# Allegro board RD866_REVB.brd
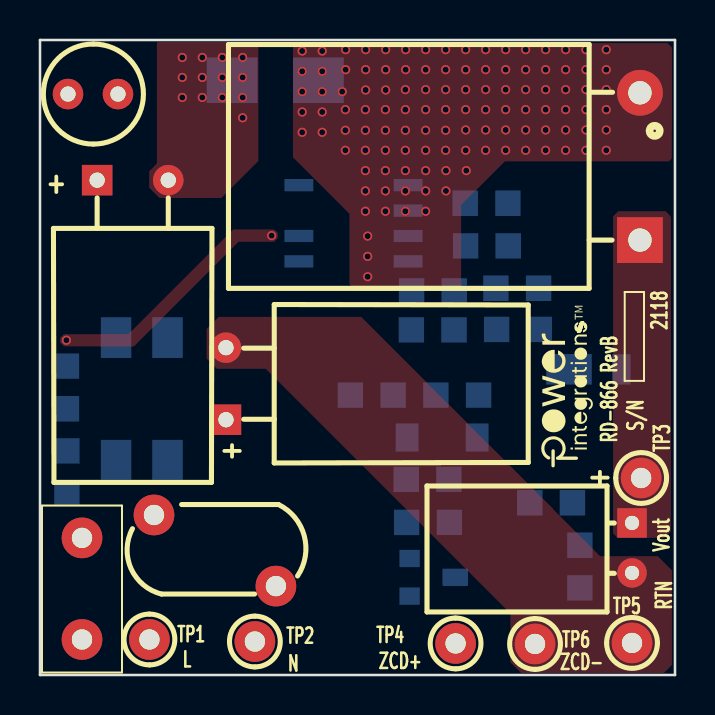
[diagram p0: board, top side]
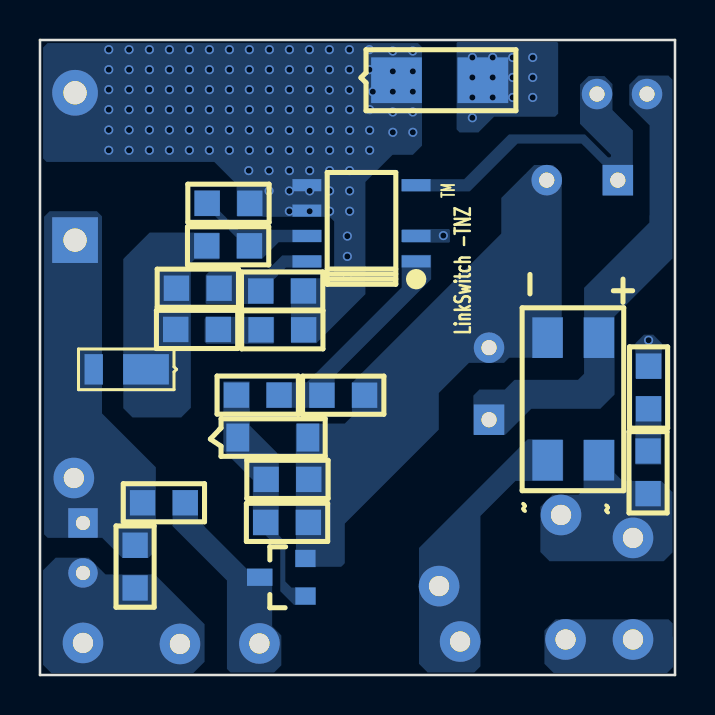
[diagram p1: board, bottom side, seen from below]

Outline 31.75 x 31.75 mm; copper layers: TOP, BOTTOM. Coordinates in mm from the lower left corner of the outline.
Outline path: 0,31.75 0,0 31.75,0 31.75,31.75 0,31.75

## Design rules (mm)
constraint set DEFAULT: min track width 0.508

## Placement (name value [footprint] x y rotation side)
BR1  B10S-G  [PISMSOIC4]  6.37 10.74 180 bottom
C1  2.2 uF  [PIPOLCAPCLYD320LS140030430H]  9.3 14.56 270 top
C2  2.2 uF  [PIPOLCAPCLYD320LS140030430H]  4.64 24.74 180 top
C3  100 pF  [PISMC0805]  17.66 13.99 180 bottom
C4  100 nF  [PISMC0805]  23.39 23.59 180 bottom
C5  10 uF  [PISMC0805]  24.96 17.28 180 bottom
C6  100 pF  [PISMC0805]  20.46 7.63 180 bottom
C7  220 uF  [PIPOLCAPCLYD6P3X9MM_H]  29.6 6.35 270 top
D1  DFLR1600-7  [PISMDDFLR120012]  26.42 15.28 180 bottom
D2  ES2J-LTP  [PISMDO214AC12]  13.92 29.74 180 bottom
F1  1 A  [PI_RST_MICROFUSE]  2.1 1.78 90 top
L1  680 uH  [PICHOKETOKINVD216H413LS098D030]  1.4 29.05 0 top
L2  680 uH  [PI_CHOKE_RL5480-4_D2]  30 21.74 90 top
NOREF  -  []  0 0 0 top
NOREF#2  -  []  31.75 0 90 top
NOREF#3  -  []  25.17 9.83 90 top
NOREF#4  -  []  -150.78 54.23 0 top
NOREF#5  -  []  -228.6 -144.78 0 top
Q1  2N7002  [PISMSOT23123_1]  18.48 5.83 90 bottom
R1  499 k  [PISMR0805]  1.35 11.2 270 bottom
R2  499 k  [PISMR0805]  1.32 15.44 270 bottom
R3  4.32 k  [PISMR0805]  21.28 21.46 0 bottom
R4  24.3 k  [PISMR0805]  24.93 19.34 180 bottom
R5  20.0 k  [PISMR0805]  20.71 19.2 180 bottom
R6  30  [PISMR0805]  20.7 17.26 180 bottom
R7  100 k  [PISMR0805]  19.8 14 0 bottom
R8  100 k  [PISMR0805]  26.62 8.61 180 bottom
R9  499 k  [PISMR0805]  18.31 9.78 0 bottom
R10  1.6 k  [PISMR0805]  27 6.49 270 bottom
RV1  300 Vac  [PIDISC350X225LS240X140040]  5.7 8 0 top
TP1  L  [PITPKEYSTONE100X100]  5.47 1.78 0 top
TP2  N  [PITPKEYSTONE100X100]  10.74 1.67 0 top
TP3  RED  [PITPKEYSTONE100X100]  30.06 9.85 90 top
TP4  ZCD Signal  [PITPKEYSTONE100X100]  20.78 1.58 0 top
TP5  BLK  [PITPKEYSTONE100X100]  29.6 1.6 90 top
TP6  BLK  [PITPKEYSTONE100X100]  24.75 1.55 0 top
U1  LNK3307  [PISMSO8_NOP3]  12.94 20.68 90 bottom
VR1  MMSZ4693T1G  [PI_SM_SOD-123_12]  21.86 11.87 180 bottom

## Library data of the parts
BR1 = DIODE BRIDGE_~~+-: alternate symbols: (pi_sm_soic4_slot)
C1 C2 = CAP POL
C3-C6 = CAP NP
C7 = CAP POL: alternate symbols: (pipolcapclyd6p3x9mm_h)
D1 D2 = DIODE
F1 = FUSE: alternate symbols: (pirstmicrofusehoz)
L1 = INDUCTOR
L2 = INDUCTOR_dot2: alternate symbols: (pi_choke_RL5480-4H_d2)
Q1 = FET_N_GSD
R1 R2 = R: room: 1
R3 R4 R6-R9 = R
R5 R10 = R: tolerance: 1%
RV1 = VARISTOR
TP1 TP2 TP4-TP6 = TESTPOINT
TP3 = TESTPOINT: room: 2
U1 = LNK-TNZ
VR1 = DIODE_ZENER

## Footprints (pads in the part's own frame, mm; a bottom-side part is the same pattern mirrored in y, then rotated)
PI_CHOKE_RL5480-4_D2
  rect 2.286x2.286 hole 1.168: 1(0,0)
  round 2.286 hole 1.168: 2(7.366,0)
PI_RST_MICROFUSE
  round 2.032 hole 1.016: 1(0,0) 2(5.08,0)
PI_SM_SOD-123_12
  rect 1.143x1.397 smd: 1(0,0) 2(3.505,0)
PICHOKETOKINVD216H413LS098D030
  round 1.524 hole 0.762: 1(0,0) 2(2.499,0)
PIDISC350X225LS240X140040
  round 2.032 hole 1.016: 1(0,0) 2(6.096,-3.556)
PIPOLCAPCLYD6P3X9MM_H
  rect 1.473x1.473 hole 0.711: 1(-1.25,0)
  round 1.473 hole 0.711: 2(1.25,0)
PIPOLCAPCLYD320LS140030430H
  rect 1.524x1.524 hole 0.762: 1(1.778,0)
  round 1.524 hole 0.762: 2(-1.778,0)
PISMC0805
  rect 1.27x1.27 smd: 1(0,0) 2(2.134,0)
PISMDDFLR120012
  rect 2.286x1.524 smd: 1(-0.025,0)
  rect 0.914x1.524 smd: 2(-2.642,0)
PISMDO214AC12
  rect 2.54x2.286 smd: 1(0,0) 2(4.318,0)
PISMR0805
  rect 1.27x1.27 smd: 1(0,0) 2(2.134,0)
PISMSO8_NOP3
  rect 0.61x1.448 smd: 1(0,0) 2(1.27,0) 4(3.81,0) 5(3.81,5.461) 6(2.54,5.461) 7(1.27,5.461) 8(0,5.461)
PISMSOIC4
  rect 1.524x2.032 smd: 1(0,0) 2(2.571,0) 3(2.571,6.129) 4(0,6.129)
PISMSOT23123_1
  rect 0.864x1.016 smd: 1(-1.88,0) 2(0,0)
  rect 0.864x1.27 smd: 3(-0.94,2.286)
PITPKEYSTONE100X100
  round 2.032 hole 1.016: 1(0,0)

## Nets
N361822: BR1.1 RV1.2 TP2.1
N361834: BR1.4 C1.2 C2.2 C3.2 C6.2 C7.2 D2.2 Q1.2(S) R9.1 R10.2 TP5.1 TP6.1 VR1.2
N595771: BR1.2 F1.2 R1.2 RV1.1
N596154: F1.1 TP1.1
N596955: C4.1 R3.1 U1.7
N596963: C5.1 D1.1 R3.2 R4.1
N597007: R4.2 R5.1 U1.8
N597039: C7.1 D1.2 L2.1 R8.1 R10.1 TP3.1
N597129: C4.2 D2.1 L2.2 R5.2 R6.2 U1.5 U1.6
N597183: C2.1 L1.2 U1.4
N605807: R2.1 U1.2
N608013: R1.1 R2.2
N610414: BR1.3 C1.1 L1.1
N4290608: Q1.3 R8.2 TP4.1
N4294463: C3.1 R7.1 U1.1
N4294503: C6.1 Q1.1 R7.2 R9.2 VR1.1
N4315295: C5.2 R6.1

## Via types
v1: diameter 0.457, hole 0.305, TOP to BOTTOM, 127 vias

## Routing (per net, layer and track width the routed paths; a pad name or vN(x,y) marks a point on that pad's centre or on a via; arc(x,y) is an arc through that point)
N361834:
  vias: v1(7.11,30.88) v1(7.11,29.88) v1(7.11,28.88) v1(8.12,30.88) v1(8.12,29.88) v1(8.12,28.88) v1(9.12,30.88) v1(9.12,29.88) v1(9.12,28.88) v1(10.13,30.88) v1(10.13,29.88) v1(10.13,28.88) v1(10.13,27.86)
N597129:
  vias: v1(13.11,31.2) v1(13.11,30.18) v1(13.11,29.17) v1(13.11,28.15) v1(13.11,27.13) v1(14.11,31.2) v1(14.11,30.18) v1(14.11,29.17) v1(14.11,28.15) v1(14.11,27.13) v1(15.11,29.17) v1(15.28,31.27) v1(15.28,30.27) v1(15.27,28.27) v1(15.27,27.24) v1(15.27,26.24) v1(16.28,31.27) v1(16.28,30.27) v1(16.28,29.25) v1(16.27,28.27) v1(16.27,27.24) v1(16.27,26.24) v1(16.27,25.22) v1(16.27,24.2) v1(16.27,23.19) v1(16.38,21.95) v1(16.38,20.93) v1(16.38,19.91) v1(17.28,31.27) v1(17.28,30.27) v1(17.28,29.25) v1(17.27,28.27) v1(17.27,27.24) v1(17.27,26.24) v1(17.27,25.22) v1(17.27,24.2) v1(17.27,23.19) v1(18.28,31.27) v1(18.28,30.27) v1(18.27,29.27) v1(18.27,28.27) v1(18.27,27.24) v1(18.27,26.24) v1(18.27,25.22) v1(18.27,24.2) v1(18.27,23.19) v1(19.28,31.27) v1(19.28,30.27) v1(19.28,29.27) v1(19.28,28.27) v1(19.28,27.24) v1(19.28,26.24) v1(19.28,25.22) v1(19.28,24.2) v1(19.28,23.19) v1(20.28,31.27) v1(20.28,30.27) v1(20.28,29.27) v1(20.28,28.27) v1(20.28,27.24) v1(20.28,26.24) v1(20.3,25.22) v1(20.3,24.2) v1(21.28,31.27) v1(21.28,30.27) v1(21.28,29.27) v1(21.28,28.27) v1(21.28,27.25) v1(21.28,26.24) v1(21.31,25.22) v1(22.28,31.27) v1(22.28,30.27) v1(22.28,29.27) v1(22.28,28.27) v1(22.28,27.25) v1(22.28,26.24) v1(23.28,31.27) v1(23.28,30.27) v1(23.28,29.27) v1(23.28,28.27) v1(23.28,27.25) v1(23.28,26.24) v1(24.28,31.27) v1(24.28,30.27) v1(24.28,29.27) v1(24.28,28.27) v1(24.28,27.25) v1(24.28,26.24) v1(25.28,31.27) v1(25.28,30.27) v1(25.28,29.27) v1(25.28,28.27) v1(25.28,27.25) v1(25.28,26.24) v1(26.28,31.27) v1(26.28,30.27) v1(26.28,29.27) v1(26.28,28.27) v1(26.28,27.25) v1(26.28,26.24) v1(27.3,31.27) v1(27.3,30.27) v1(27.3,29.27) v1(27.3,28.27) v1(27.3,27.25) v1(27.3,26.24) v1(28.31,31.27) v1(28.31,30.27) v1(28.31,29.27) v1(28.31,28.27) v1(28.31,27.25) v1(28.31,26.24)
N605807:
  vias: v1(1.32,16.74) v1(11.58,21.97)

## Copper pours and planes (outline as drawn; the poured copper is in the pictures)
N361822 on BOTTOM: 7.37,11.79 12.8,6.35 12.8,0.56 12.37,0.13 10.03,0.13 9.73,0.43 9.73,7.95 7.98,9.7 5.61,9.7 5.59,9.73 5.59,11.73 5.64,11.79
N361834 on TOP: 5.46,25.2 5.84,25.58 5.84,31.6 5.89,31.65 10.87,31.65 10.92,31.6 10.92,25.7 9.07,23.85 5.97,23.85 5.46,24.36
N361834 on TOP: 25.65,8.29 28.01,5.94 30.89,5.94 31.6,5.23 31.6,0.51 31.19,0.1 24.05,0.1 23.52,0.64 23.52,3.07 11.28,15.32 8.84,15.32 8.33,15.82 8.33,17.3 8.94,17.91 16.05,17.91 25.65,8.31
N361834 on BOTTOM: 6.1,25.5 7.04,25.5 8.69,23.85 8.69,22.07 16.15,14.61 16.15,12.93 16.51,12.57 18.9,12.57 18.96,12.51 18.96,7.24 18.95,7.23 18.95,5.44 18.92,5.41 16.69,5.41 16.51,5.59 16.51,7.57 11.81,12.27 11.81,14.1 10.3,15.61 8.55,15.61 8.29,15.86 5.73,15.86 5.66,15.93 5.66,25.07
N361834 on BOTTOM: 9.83,27.13 9.04,27.91 5.99,27.91 5.84,28.07 5.84,31.6 5.89,31.65 10.87,31.65 10.92,31.6 10.92,27.28 10.77,27.13
N361834 on BOTTOM: 31.6,5.23 31.6,0.51 31.19,0.1 24.08,0.1 23.52,0.66 23.52,2.54 26.01,5.03 28.47,5.03 29.31,5.87 30.96,5.87
N595771 on BOTTOM: 0.56,5.69 0.13,6.12 0.13,9.14 0.69,9.7 2.62,9.7 3.02,10.11 3.02,11.76 4.57,11.76 4.57,9.27 4.83,9.02 6.12,9.02 6.73,8.41 6.73,6.15 6.27,5.69
N596154 on BOTTOM: 0.4,0.1 0.1,0.4 0.1,1.9 0.11,1.92 0.11,2.58 0.32,2.78 5.97,2.78 6.53,2.22 6.53,0.56 6.07,0.1
N596955 on BOTTOM: 21.83,22.26 22.76,23.19 22.76,24.23 24,24.23 24.03,24.21 24.03,22.94 22.99,22.94 21.92,21.87 21.92,20.83 20.62,20.83 19.81,21.64 17.68,21.64 17.68,22.26
N596963 on BOTTOM: 24.21,20.6 24.03,20.78 22.81,20.78 22.78,20.8 22.78,22.12 26.26,22.12 27.58,20.8 27.58,13.34 27.13,12.88 24.69,12.88 24.21,13.36
N597007 on BOTTOM: 17.68,20.98 19.63,20.98 20.45,20.17 23.29,20.17 23.47,19.99 23.47,18.59 23.43,18.55 20.21,18.55 20.07,18.69 20.07,19.76 19.46,20.37 17.68,20.37
N597039 on TOP: 31.55,22.91 31.55,7.19 31.22,6.86 28.88,6.86 28.65,7.09 28.65,22.94 28.91,23.19 31.27,23.19
N597039 on BOTTOM: 31.55,22.91 31.27,23.19 28.91,23.19 28.65,22.94 28.65,13.08 25.96,10.39 25.96,6.22 26.33,5.85 27.64,5.85 28.64,6.86 31.37,6.86 31.55,7.04
N597129 on TOP: 31.6,31.37 31.6,27.23 31.58,27.22 31.58,25.82 31.45,25.68 23.24,25.68 21.06,23.5 21.06,19.41 20.85,19.2 15.8,19.2 15.47,19.53 15.47,23.06 12.65,25.88 12.65,31.39 12.85,31.6 31.37,31.6
N597129 on BOTTOM: 31.37,31.6 31.6,31.37 31.6,25.83 31.42,25.65 23.04,25.65 21.92,24.54 21.92,22.96 21.87,22.91 17.27,22.91 17.04,22.68 17.04,20.07 17.27,19.84 19.2,19.84 19.2,16.64 19.15,16.59 17.93,16.59 15.48,19.04 15.48,24.65 14.12,26.01 13.11,26.01 12.65,26.47 12.65,31.39 12.85,31.6
N597183 on BOTTOM: 3.61,23.98 3.61,25.5 4.67,26.57 7.87,26.57 10.26,24.18 13.67,24.18 13.68,24.19 13.68,24.79 10.54,24.79 8.31,27.03 4.5,27.03 3.35,25.88 3.25,25.88 3.2,25.93 3.2,26.01 4.75,27.56 4.75,29.51 4.32,29.95 3.53,29.95 3.12,29.54 3.12,28.24 2.11,27.23 2.11,23.98
N605807 on TOP: 4.42,17.04 9.65,22.28 11.71,22.28 11.89,22.1 11.89,21.84 11.71,21.67 9.93,21.67 4.7,16.43 1.19,16.43 1.02,16.61 1.02,16.87 1.19,17.04
N605807 on BOTTOM: 11.3,22.3 13.61,22.3 13.67,22.25 13.67,21.67 13.61,21.62 11.3,21.62 11.25,21.67 11.25,22.25
N605807 on BOTTOM: 0.66,14.81 0.66,16.59 1.09,17.02 1.55,17.02 1.98,16.59 1.98,14.86 1.93,14.81
N608013 on BOTTOM: 0.69,13.94 1.98,13.94 1.98,10.54 1.96,10.52 0.69,10.52
N610414 on BOTTOM: 10.03,12.01 8.48,12.01 7.19,13.31 3.73,13.31 3.02,14.02 3.02,17.93 0.13,20.83 0.13,29.77 0.33,29.97 1.83,29.97 2.29,29.51 2.29,28.5 1.27,27.48 1.27,22.99 1.28,22.97 1.28,22.62 4.55,19.35 4.55,15.06 4.85,14.76 8.03,14.76 8.51,14.27 9.78,14.27 10.08,13.97 10.08,12.06
N4290608 on BOTTOM: 25.15,7.47 22.4,4.72 22.4,0.3 22.23,0.13 20.04,0.13 19.68,0.48 19.68,1.98 20.14,2.44 20.14,5.31 21.41,5.31 23.52,7.42 23.52,7.44 23.85,7.77 23.85,9.25 25.12,9.25 25.12,7.49
N4294463 on BOTTOM: 17.02,14.96 12.19,19.79 12.19,21.01 13.67,21.01 13.67,19.38 18.41,14.63 20.42,14.63 20.42,13.36 17.02,13.36
N4294503 on BOTTOM: 19.81,11.02 21.26,12.47 21.26,14.66 21.29,14.68 22.58,14.68 22.58,11.23 21.11,9.75 21.11,6.99 20.47,6.99 19.74,6.25 19.74,4.19 19.05,3.51 17.96,3.51 17.96,4.37 19.18,4.37 19.48,4.67 19.48,6.65 19.81,6.99
N4315295 on BOTTOM: 20.04,17.91 23.42,17.91 23.52,17.81 23.52,16.66 23.42,16.56 20.09,16.56 20.04,16.61

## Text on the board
Ref Des/Silkscreen Bottom: TM | LinkSwitch -TNZ
Ref Des/Silkscreen Top: TP1 | L | TP2 | N | TP4 | ZCD+ | ZCD- | TP6 | TP5 | RD-866 RevB | S/N | 2118 | Vout | TP3 | RTN
User.5: 14.  FAB HOUSE LOGO,DATE CODE TO BE IN SILK SCREEN ONLY.DO NOT USE COPPER. | 13.  MATERIAL FR4 COPPER 2oz THICKNESS 0.039" | PLEASE DELETE THIS PIN
User.8: FIGURE | FINISHED_SIZE | 12.0 | 28.0 | 30.0 | 40.0 | 46.0 | DRILL CHART: TOP to BOTTOM | ALL UNITS ARE IN MILS | TOLERANCE_DRILL | +3.0/-3.0 | PLATED | QTY | 127 | 2 | 6 | 10 | 147 | TOTAL HOLES:
